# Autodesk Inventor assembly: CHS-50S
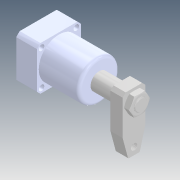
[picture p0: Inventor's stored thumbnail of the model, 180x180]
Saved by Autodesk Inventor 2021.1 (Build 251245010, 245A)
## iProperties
Created: 2020-02
Part Number: CHS-50S
Description: STEP AP214
Document SubType Name: Assembly
Designer: user
Title: chs-50s_asm.STEP
Revision Number: ÈÎºÎ
Sending System: SolidWorks 2016
Preprocessor: SwSTEP 2.0
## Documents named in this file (5)
- D:\Vault_2016\Projekty\Clamptek\Hydraulic\CHS\CHS-50\Inventor\CHS-50S\CHS-50S.iam
- D:\Vault_2016\Projekty\Clamptek\Hydraulic\CHS\CHS-50\Inventor\CHS-50S\CHS-50BT.ipt
- D:\Vault_2016\Projekty\Clamptek\Hydraulic\CHS\CHS-50\Inventor\CHS-50S\CHS-50SHSG.ipt
- D:\Vault_2016\Projekty\Clamptek\Hydraulic\CHS\CHS-50\Inventor\CHS-50S\CHS-50SYB.ipt
- D:\Vault_2016\Projekty\Clamptek\Hydraulic\CHS\CHS-50\Inventor\CHS-50S\M20LM.ipt
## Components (4 placed, 4 different names)
1. CHS-50BT_1
2. CHS-50SHSG_2
3. CHS-50SYB_3
4. M20LM_4
